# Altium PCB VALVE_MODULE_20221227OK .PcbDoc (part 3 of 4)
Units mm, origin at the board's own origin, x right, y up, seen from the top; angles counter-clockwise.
Board outline 260.15 x 142.01 mm, 2 copper layers (Top Layer, Bottom Layer); 455 components, 212 nets, 1302 pads, 385 vias.
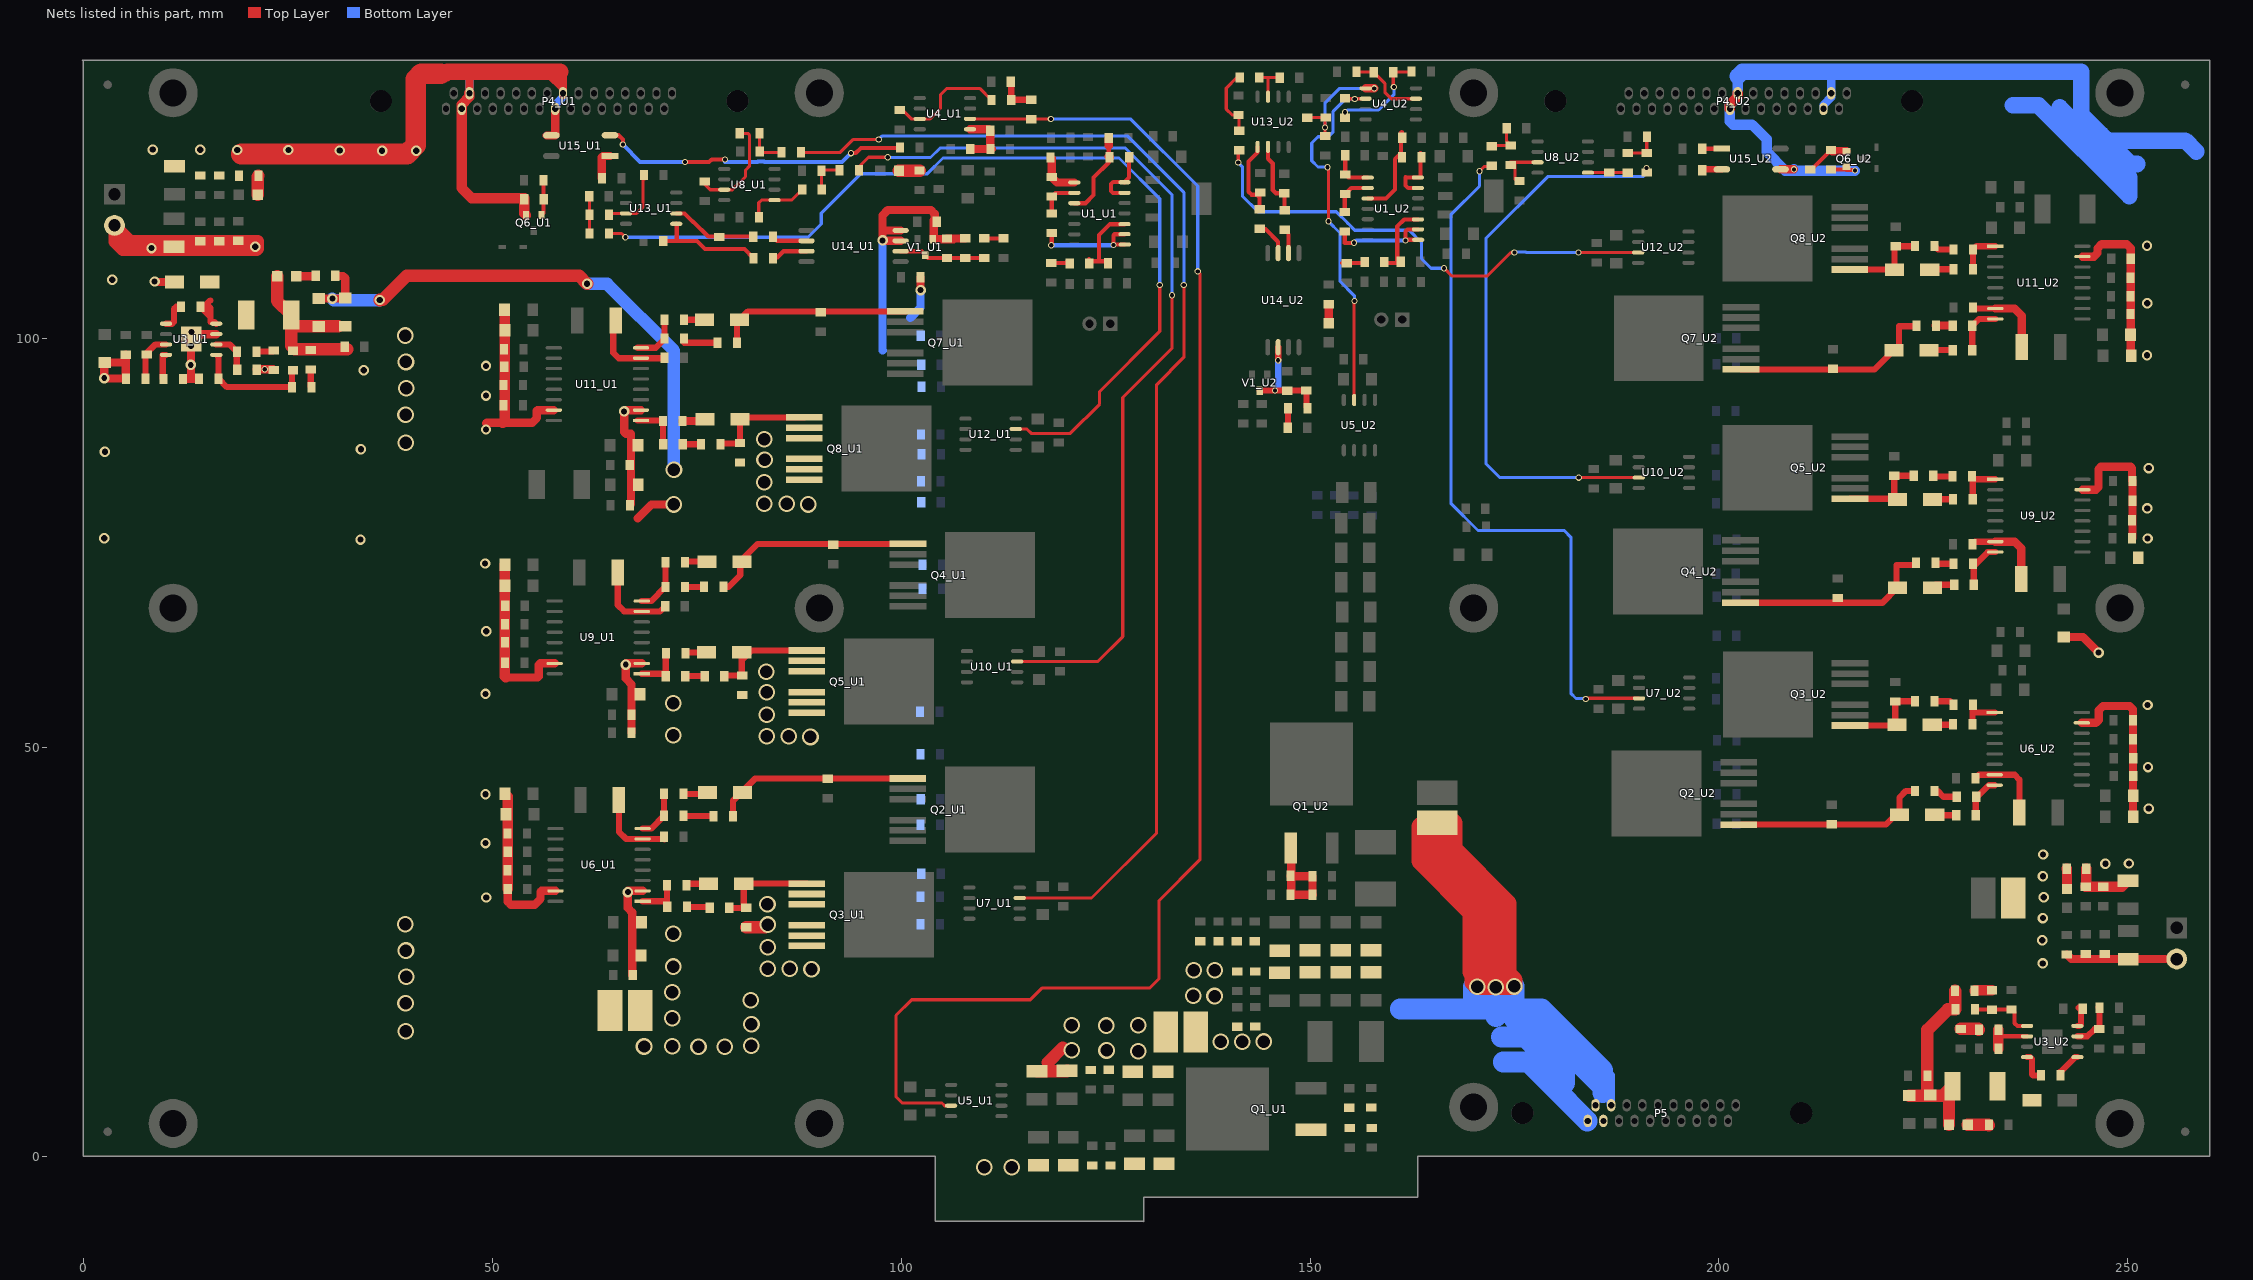
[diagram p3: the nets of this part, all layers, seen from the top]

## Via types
v1: diameter 0.762, hole 0.508, Top Layer to Bottom Layer, 142 vias
v2: diameter 2.032, hole 1.524, Top Layer to Bottom Layer, 140 vias
v3: diameter 1.27, hole 0.762, Top Layer to Bottom Layer, 77 vias
v4: diameter 1.27, hole 0.711, Top Layer to Bottom Layer, 14 vias
v5: diameter 1.778, hole 1.27, Top Layer to Bottom Layer, 12 vias

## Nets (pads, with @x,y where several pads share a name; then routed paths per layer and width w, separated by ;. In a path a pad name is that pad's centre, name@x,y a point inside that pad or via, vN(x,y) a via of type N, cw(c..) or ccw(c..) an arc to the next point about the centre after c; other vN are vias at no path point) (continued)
ISO_GND_U1: C5_U1.2 C6_U1.2 C7_U1.1 C8_U1.1 C9_U1.1 C10_U1.1 C11_U1.1 C41_U1.2 C42_U1.2 C43_U1.2 C44_U1.2 C49_U1.2 C50_U1.2 C51_U1.2 C52_U1.2 C66_U1.2 C67_U1.2 C68_U1.2 C103_U1.2 P2_U1.2 P4_U1.2 P4_U1.8 P4_U1.17 P4_U1.23 Q6_U1.2 R8_U1.1 R21_U1.1 R31_U1.2 R33_U1.2 R48_U1.2 R50_U1.2 R58_U1.1 R63_U1.2 R65_U1.2 U6_U1.15 U9_U1.15 U11_U1.15 U15_U1.4 | length 214.5
  Top Layer w1.016: P4_U1.17@47.231,129.952 47.231,131.788 47.625,132.182 57.048,132.182 ; 49.276,89.611 49.352,89.687 51.308,89.687 54.915,89.687 54.915,89.713 55.474,90.272 55.474,91.135 55.55,91.211 U11_U1.15@57.549,91.211 ; 51.689,58.547 51.714,58.522 55.575,58.522 55.702,58.649 55.702,60.046 55.905,60.249 U9_U1.15@57.651,60.249 ; R33_U1.2@51.918,32.664 51.918,31.115 52.273,30.759 55.22,30.759 55.931,31.471 55.931,32.334 56.032,32.436 U6_U1.15@57.752,32.436 ; R58_U1.1@53.924,117.018 R58_U1.1@53.924,117.119 ; U15_U1.4@56.693,124.79 57.683,124.79 57.709,124.816 P4_U1.8@57.709,128.047 ; P4_U1.23@58.661,129.952 P4_U1.23@58.661,130.569 ; 57.048,132.182 P4_U1.23@58.661,130.569 ; 57.048,132.182 58.344,132.182 58.661,131.864 P4_U1.23@58.661,130.569
  Top Layer w1.27: P4_U1.17@47.231,129.952 47.231,129.527 46.279,128.575 P4_U1.2@46.279,128.047 46.279,118.364 47.523,117.119 R58_U1.1@53.924,117.119 ; 51.308,89.687 51.537,89.916 C66_U1.2@51.537,103.48 ; C49_U1.2@51.562,72.288 C50_U1.2@51.562,69.723 C52_U1.2@51.562,65.049 R48_U1.2@51.562,62.814 R50_U1.2@51.562,60.35 51.562,58.674 51.689,58.547 ; C41_U1.2@51.587,44.298 51.918,43.967 C43_U1.2@51.918,37.211 R33_U1.2@51.918,32.664 ; R58_U1.1@53.924,117.018 53.924,115.291 Q6_U1.2@54.153,115.062
  Top Layer w1.524: 3.835,111.811 P2_U1.2@3.835,113.792 5.74,111.887 21.336,111.887 21.336,110.922 21.234,110.82 4.826,110.82 3.835,111.811
  Top Layer w2.032: 43.688,132.349 44.272,132.349 44.526,132.603 58.344,132.603
  Top Layer w2.54: 19.329,122.53 39.599,122.53 40.665,123.596 40.665,131.674 41.341,132.349 43.688,132.349
  Bottom Layer w1.016: P4_U1.17@47.231,129.952 47.231,131.788 47.701,132.258 58.369,132.258 58.661,131.966 P4_U1.23@58.661,129.952 58.661,129.476 57.709,128.524 P4_U1.8@57.709,128.047
  other v2: 39.446,15.265 39.421,18.694 39.497,21.92 39.472,25.146 39.37,28.372 39.446,87.224 39.421,90.653 39.497,93.878 39.472,97.104 39.37,100.33
  other v3: 49.276,31.623 49.2,38.278 49.2,44.247 49.2,56.515 49.276,64.186 49.149,72.466 49.251,88.849 49.251,92.989 49.251,96.622 8.357,111.023 21.031,111.201 36.551,122.911 40.716,122.911 31.369,122.961 18.847,123.012 25.095,123.012 14.326,123.038 8.509,123.063
ISO_GND_U2: C5_U2.2 C6_U2.2 C7_U2.1 C8_U2.1 C9_U2.1 C10_U2.1 C11_U2.1 C41_U2.2 C42_U2.2 C43_U2.2 C44_U2.2 C49_U2.2 C50_U2.2 C51_U2.2 C52_U2.2 C66_U2.2 C67_U2.2 C68_U2.2 C103_U2.2 P2_U2.2 P4_U2.2 P4_U2.8 P4_U2.17 P4_U2.23 Q6_U2.2 R8_U2.1 R21_U2.1 R31_U2.2 R33_U2.2 R48_U2.2 R50_U2.2 R58_U2.1 R63_U2.2 R65_U2.2 U6_U2.15 U9_U2.15 U11_U2.15 U15_U2.4 | length 228.2
  Top Layer w0.508: R58_U2.1@213.69,120.625 Q6_U2.2@215.24,120.625 ; Q6_U2.2@215.595,120.98 Q6_U2.2@215.24,120.625 ; v1(216.611,120.498) 216.611,120.548 216.586,120.574 215.57,120.574 215.519,120.625 Q6_U2.2@215.24,120.625
  Top Layer w1.016: U15_U2.4@207.518,120.65 v1(209.169,120.65) ; C50_U2.2@242.164,63.475 244.5,63.475 v3(246.405,61.57) ; C8_U2.1@242.519,24.663 243.078,24.105 C5_U2.2@250.038,24.105 P2_U2.2@255.956,24.105 ; U6_U2.15@244.355,52.984 246.075,52.984 246.431,53.34 246.431,54.534 246.939,55.042 250.215,55.042 250.622,54.635 R33_U2.2@250.622,53.315 R31_U2.2@250.622,50.952 250.622,41.504 C42_U2.2@250.647,41.478 ; U9_U2.15@244.432,81.483 246.101,81.483 246.405,81.788 246.405,83.998 246.685,84.277 250.342,84.277 250.495,84.125 250.495,82.601 R50_U2.2@250.546,82.55 R48_U2.2@250.546,80.112 250.546,75.59 C51_U2.2@250.495,75.54 ; U11_U2.15@244.432,109.982 245.847,109.982 246.278,110.414 246.278,110.998 246.786,111.506 249.834,111.506 250.342,110.998 R65_U2.2@250.342,109.703 250.342,97.892 C66_U2.2@250.393,97.841
  Top Layer w1.27: P4_U2.23@201.336,128.047 201.336,128.565 202.288,129.517 P4_U2.8@202.288,129.952 ; R8_U2.1@244.907,35.154 244.907,33.02 C7_U2.1@244.831,32.944 C11_U2.1@246.964,32.944 249.25,32.944 C6_U2.2@249.987,33.68
  Bottom Layer w1.016: P4_U2.17@212.766,128.047 212.766,128.514 213.718,129.466 P4_U2.2@213.718,129.952 213.718,132.56 213.69,132.588
  Bottom Layer w1.27: 202.311,132.029 202.288,132.006 P4_U2.8@202.288,129.952 202.288,129.441 201.336,128.489 P4_U2.23@201.336,128.047 201.336,126.502 201.727,126.111 204.038,126.111 205.816,124.333 205.816,122.784 208.102,120.498 v1@209.321,120.498 ; v1(209.169,120.65) v1@209.321,120.498 ; v1(216.611,120.498) v1@209.321,120.498
  Bottom Layer w2.032: 202.311,132.029 202.87,132.588 213.69,132.588 244.272,132.588 244.272,127.381 ; 235.941,128.499 235.941,128.473 239.065,128.473 250.165,117.373 250.165,119.685 244.272,125.578 244.272,125.628 ; 241.656,128.245 244.272,125.628 ; 251.155,121.31 250.342,121.31 247.498,124.155 ; 258.343,122.834 257.023,124.155 247.498,124.155 ; 244.272,125.628 244.272,127.381 ; 244.272,125.628 244.958,124.943 246.71,124.943 ; 244.272,127.381 246.71,124.943 ; 246.71,124.943 247.498,124.155
  other v3: 239.573,23.571 239.522,26.416 239.598,29.108 239.7,31.648 239.598,34.239 247.244,35.763 250.114,35.789 239.624,36.881 252.552,42.494 252.451,47.574 252.4,55.169 252.4,75.514 252.349,79.197 252.527,84.125 252.324,97.917 252.349,104.292 252.324,111.303
NetC13_U1_1: C13_U1.1 D2_U1.2 L1_U1.2 U3_U1.8 | length 6.6
  Top Layer w0.762: 15.57,104.623 C13_U1.1@14.808,103.861 ; U3_U1.8@16.281,101.778 16.078,101.981 15.57,101.981 15.57,102.641 ; C13_U1.1@14.808,103.861 C13_U1.1@14.351,103.861 15.57,102.641 ; C13_U1.1@14.808,103.861 15.418,103.861 15.57,103.708 15.57,102.641
NetC13_U1_2: C13_U1.2 U3_U1.1 | length 3.6
  Top Layer w0.762: U3_U1.1@10.135,101.778 10.871,101.778 11.1,102.006 11.1,103.581 11.379,103.861 C13_U1.2@11.963,103.861
NetC13_U2_1: C13_U2.1 D2_U2.2 L1_U2.2 U3_U2.8 | length 3.7
  Top Layer w0.762: U3_U2.8@237.668,12.116 238.023,12.116 238.277,11.862 238.277,9.982 238.379,9.881 C13_U2.1@239.37,9.881
NetC13_U2_2: C13_U2.2 U3_U2.1 | length 3.3
  Top Layer w0.762: C13_U2.2@241.757,9.881 241.757,10.338 243.535,12.116 U3_U2.1@243.815,12.116
NetC14_U1_1: C14_U1.1 R13_U1.1 R14_U1.2 U4_U1.5 | length 7.5
  Top Layer w1.016: U4_U1.5@108.433,125.552 110.719,125.552 C14_U1.1@110.896,125.374 110.896,123.317 111.074,123.139 R13_U1.1@108.458,123.139
NetC14_U2_1: C14_U2.1 R13_U2.1 R14_U2.2 U4_U2.5 | length 15.2
  Top Layer w0.381: C14_U2.1@149.682,126.975 R14_U2.2@151.917,126.975 ; R13_U2.1@151.841,124.714 R14_U2.2@151.841,126.822
  Top Layer w1.016: U4_U2.5@156.794,130.556 v1(157.861,130.556)
  Bottom Layer w0.381: v1(151.816,125.781) 151.816,128.753 153.619,130.556 v1(157.861,130.556)
NetC21_U1_1: C21_U1.1 C22_U1.1 C23_U1.1 D3_U1.1 L1_U1.1 R20_U1.2 R40_U1.1 | length 22.1
  Top Layer w1.524: D3_U1.1@23.724,107.569 23.724,104.572 L1_U1.1@25.451,102.845 25.451,101.092 ; 31.217,101.448 25.806,101.448 25.451,101.092 ; R40_U1.1@32.309,98.679 30.124,98.679 25.857,98.679 25.451,99.085 25.451,101.092
NetC21_U2_1: C21_U2.1 C22_U2.1 C23_U2.1 D3_U2.1 L1_U2.1 R20_U2.2 R40_U2.1 | length 24.9
  Top Layer w1.524: C22_U2.1@223.241,7.417 227.406,7.417 L1_U2.1@228.117,8.128 ; C21_U2.1@225.806,7.468 225.476,7.798 R40_U2.1@225.476,9.855 225.476,15.443 227.99,17.958 C23_U2.1@228.905,17.958 228.905,20.193 R20_U2.2@228.854,20.244 ; D3_U2.1@228.117,3.861 L1_U2.1@228.117,8.128 ; L1_U2.1@228.549,8.56 L1_U2.1@228.117,8.128
NetC23_U1_2: C23_U1.2 R19_U1.1 R22_U1.2 U3_U1.5 | length 14.2
  Top Layer w0.762: 16.535,97.714 16.561,97.688 R22_U1.2@16.561,95.047 17.577,94.031 R19_U1.1@25.552,94.031 25.552,95.987 C23_U1.2@25.654,96.088
NetC23_U2_2: C23_U2.2 R19_U2.1 R22_U2.2 U3_U2.5 | length 8
  Top Layer w0.508: C23_U2.2@231.292,17.958 231.318,17.932 R22_U2.2@235.763,17.932 236.144,17.551 236.144,16.256 236.499,15.9 236.525,15.926 U3_U2.5@237.668,15.926
NetC26_U1_2: C26_U1.2 U3_U1.4 | length 3.4
  Top Layer w0.762: C26_U1.2@9.83,95.021 9.728,95.123 9.728,97.942 10.109,97.942 U3_U1.4@10.135,97.968
NetC26_U2_2: C26_U2.2 U3_U2.4 | length 2.7
  Top Layer w0.762: U3_U2.4@243.815,15.926 244.069,15.926 244.246,16.104 244.246,17.907 C26_U2.2@243.992,18.161
NetC27_U1_2: C27_U1.2 C28_U1.2 U3_U1.6 | length 5.1
  Top Layer w0.762: U3_U1.6@16.281,99.238 17.932,99.238 C28_U1.2@18.796,98.374 18.796,96.266 C27_U1.2@18.847,96.215
NetC27_U2_2: C27_U2.2 C28_U2.2 U3_U2.6 | length 5.8
  Top Layer w0.508: 234.163,14.656 U3_U2.6@237.668,14.656
  Top Layer w1.27: C27_U2.2@234.163,13.157 234.163,14.656 C28_U2.2@234.163,15.469
NetC28_U1_1: C28_U1.1 R25_U1.2 | length 2.2
  Top Layer w0.762: C28_U1.1@21.184,98.374 23.19,98.374 R25_U1.2@23.317,98.501
NetC28_U2_1: C28_U2.1 R25_U2.2 | length 2.3
  Top Layer w1.524: R25_U2.2@229.54,15.57 231.673,15.57 C28_U2.1@231.775,15.469
NetC31_U1_1: C31_U1.1 R28_U1.2 R29_U1.1 | length 4.7
  Top Layer w0.762: C31_U1.1@113.411,131.343 113.462,131.293 R28_U1.2@113.462,129.134 113.487,129.159 R29_U1.1@115.926,129.159
NetC31_U2_1: C31_U2.1 R28_U2.2 R29_U2.1 | length 12.5
  Top Layer w0.381: R29_U2.1@154.28,127.152 v1(154.28,127.635) v1@154.28,127.711 ; v1(160.249,130.708) 160.172,130.785 R28_U2.2@160.172,132.537 160.198,132.563 162.357,132.563 C31_U2.1@162.408,132.613
  Bottom Layer w0.381: v1(154.28,127.635) 154.559,127.914 158.394,127.914 160.249,129.769 v1(160.249,130.708)
NetC32_U1_1: C32_U1.1 D6_U1.2 U6_U1.7 | length 9.8
  Top Layer w0.762: D6_U1.2@65.507,43.561 65.507,39.649 66.37,38.786 U6_U1.7@68.402,38.786 71.044,38.786 C32_U1.1@71.069,38.76
NetC32_U2_1: C32_U2.1 D6_U2.2 U6_U2.7 | length 9.8
  Top Layer w0.762: C32_U2.1@231.369,46.228 231.775,46.634 U6_U2.7@233.705,46.634 236.144,46.634 236.728,46.05 D6_U2.2@236.728,42.012
NetC33_U1_1: C33_U1.1 R28_U1.1 U4_U1.3 | length 14.9
  Top Layer w0.381: C33_U1.1@99.822,127.914 99.885,127.978 100.089,127.978 101.244,126.822 U4_U1.3@102.286,126.822 103.556,126.822 104.826,128.092 104.826,129.769 105.613,130.556 109.601,130.556 111.023,129.134 R28_U1.1@111.074,129.134
NetC33_U2_1: C33_U2.1 R28_U2.1 U4_U2.3 | length 9.3
  Top Layer w0.381: C33_U2.1@155.677,132.563 157.759,132.563 R28_U2.1@157.785,132.537 159.156,131.166 159.156,130.073 159.944,129.286 U4_U2.3@162.941,129.286
NetC45_U1_1: C45_U1.1 R43_U1.2 R44_U1.1 | length 4.9
  Top Layer w0.381: R43_U1.2@82.677,125.044 82.677,122.885 C45_U1.1@82.728,122.834 82.829,122.733 R44_U1.1@85.369,122.733
NetC45_U2_1: C45_U2.1 R43_U2.2 R44_U2.1 | length 4.5
  Top Layer w0.381: R44_U2.1@172.339,123.571 R43_U2.2@174.549,123.571 174.041,124.079 C45_U2.1@174.041,125.679
NetC46_U1_1: C46_U1.1 R43_U1.1 U8_U1.3 | length 13
  Top Layer w0.381: C46_U1.1@75.641,119.177 76.657,118.161 U8_U1.3@78.384,118.161 79.375,118.161 80.975,119.761 80.975,120.548 81.458,121.031 81.458,124.866 81.28,125.044 R43_U1.1@80.289,125.044
NetC46_U2_1: C46_U2.1 R43_U2.1 U8_U2.3 | length 5.5
  Top Layer w0.381: R43_U2.1@174.447,121.514 R43_U2.1@175.133,121.514 ; C46_U2.1@175.057,119.431 175.057,121.437 R43_U2.1@175.133,121.514 ; U8_U2.3@177.825,121.514 R43_U2.1@175.133,121.514
NetC47_U1_2: C47_U1.2 D11_U1.2 U9_U1.7 | length 10.4
  Top Layer w0.762: D11_U1.2@65.354,71.374 65.354,67.386 66.142,66.599 U9_U1.7@68.301,66.599 70.536,66.599 C47_U1.2@71.171,67.234
NetC47_U2_2: C47_U2.2 D11_U2.2 U9_U2.7 | length 10.2
  Top Layer w0.762: C47_U2.2@230.988,74.828 231.292,75.133 U9_U2.7@233.782,75.133
  Top Layer w1.016: U9_U2.7@233.782,75.133 236.144,75.133 236.957,74.32 D11_U2.2@236.957,70.561
NetC48_U1_1: C48_U1.1 R56_U1.2 R57_U1.1 | length 4.5
  Top Layer w0.381: R56_U1.2@90.297,118.186 90.272,118.212 C48_U1.1@90.272,120.472 90.348,120.548 R57_U1.1@92.456,120.548
NetC48_U2_1: C48_U2.1 R56_U2.2 R57_U2.1 | length 4.3
  Top Layer w0.381: R56_U2.2@188.849,122.631 191.135,122.631 R57_U2.1@191.16,122.657 191.16,124.587 C48_U2.1@191.211,124.638
NetC53_U1_1: C53_U1.1 R56_U1.1 U8_U1.5 | length 7.8
  Top Layer w0.381: C53_U1.1@82.652,114.783 82.601,114.833 82.601,116.561 82.931,116.891 U8_U1.5@84.531,116.891 86.614,116.891 R56_U1.1@87.909,118.186
NetC53_U2_1: C53_U2.1 R56_U2.1 U8_U2.5 | length 4.9
  Top Layer w0.381: U8_U2.5@183.972,120.244 R56_U2.1@188.849,120.244
NetC54_U1_2: C54_U1.2 D16_U1.2 U11_U1.7 | length 10.7
  Top Layer w0.762: D16_U1.2@64.821,102.667 64.821,98.222 65.481,97.561 67.767,97.561 C54_U1.2@70.841,97.561
NetC54_U2_2: C54_U2.2 D16_U2.2 U11_U2.7 | length 10.2
  Top Layer w0.762: C54_U2.2@231.064,103.759 231.191,103.632 U11_U2.7@233.782,103.632
  Top Layer w1.016: U11_U2.7@233.782,103.632 236.144,103.632 237.007,102.768 D16_U2.2@237.007,98.958
NetC61_U1_1: C61_U1.1 R69_U1.2 R70_U1.1 | length 4.6
  Top Layer w0.381: C61_U1.1@61.874,117.348 61.9,117.323 R69_U1.2@61.9,115.087 R70_U1.1@61.9,112.801
NetC61_U2_1: C61_U2.1 R69_U2.2 R70_U2.1 | length 8.5
  Top Layer w0.381: R70_U2.1@141.326,125.374 141.326,127.229 C61_U2.1@141.249,127.305 140.462,127.305 139.751,128.016 139.751,130.581 141.046,131.877 R69_U2.2@141.402,131.877
NetC64_U1_1: C64_U1.1 R69_U1.1 U13_U1.3 | length 8.2
  Top Layer w0.381: R69_U1.1@64.287,115.087 64.465,115.265 U13_U1.3@66.37,115.265 67.666,115.265 68.428,116.027 68.428,119.456 C64_U1.1@68.707,119.456
NetC64_U2_1: C64_U2.1 R69_U2.1 U13_U2.3 | length 4.8
  Top Layer w0.381: R69_U2.1@143.789,131.877 146.279,131.877 C64_U2.1@146.304,131.851 ; U13_U2.3@144.856,129.54 144.856,131.775
NetC69_U1_2: C69_U1.2 R75_U1.2 R76_U1.1 U14_U1.2 V1_U1.3 | length 10.6
  Top Layer w0.508: U14_U1.2@99.949,110.642 102.489,110.642 V1_U1.3@102.946,110.185 103.302,109.83 R76_U1.1@107.848,109.83 R75_U1.2@110.185,109.83
NetC69_U2_2: C69_U2.2 R75_U2.2 R76_U2.1 U14_U2.2 V1_U2.3 | length 13.4
  Top Layer w0.762: V1_U2.3@143.84,93.599 R76_U2.1@149.555,93.599 149.555,91.592 R75_U2.2@149.708,91.44 ; v1(146.101,97.307) U14_U2.2@146.101,98.908
  Bottom Layer w0.762: v1(145.72,93.624) 146.101,94.005 v1(146.101,97.307)
NetD1_U1_2: D1_U1.2 R8_U1.2 | length 2.4
  Top Layer w1.524: D1_U1.2@21.336,117.551 21.336,119.761 R8_U1.2@21.438,119.863
NetD1_U2_2: D1_U2.2 R8_U2.2 | length 2.5
  Top Layer w1.27: R8_U2.2@242.519,35.154 242.545,35.128 D1_U2.2@242.545,32.664
NetD3_U1_2: D3_U1.2 R16_U1.1 | length 2.4
  Top Layer w1.016: D3_U1.2@26.035,107.569 28.397,107.569 R16_U1.1@28.448,107.62
NetD3_U2_2: D3_U2.2 R16_U2.1 | length 2.6
  Top Layer w1.524: D3_U2.2@230.429,3.861 232.943,3.861 R16_U2.1@232.994,3.81
NetD5_U1_1: D5_U1.1 Q2_U1.1 R27_U1.2 R30_U1.1 | length 24.4
  Top Layer w0.762: R27_U1.2@79.451,41.58 79.451,43.459 82.169,46.177 Q2_U1.1@100.813,46.177
NetD5_U1_2: D5_U1.2 R23_U1.2 | length 3.1
  Top Layer w0.762: R23_U1.2@73.33,44.298 76.142,44.298 D5_U1.2@76.32,44.475
NetD5_U2_1: D5_U2.1 Q2_U2.1 R27_U2.2 R30_U2.1 | length 23.9
  Top Layer w0.762: Q2_U2.1@202.413,40.538 220.396,40.538 D5_U2.1@221.539,41.681 ; D5_U2.1@222.072,41.758 222.072,43.866 222.86,44.653 R27_U2.2@223.952,44.653
NetD5_U2_2: D5_U2.2 R23_U2.2 | length 3.2
  Top Layer w0.762: D5_U2.2@225.839,41.681 R23_U2.2@229.006,41.681
NetD9_U1_1: D9_U1.1 Q3_U1.1 R36_U1.2 R37_U1.2 | length 12.4
  Top Layer w0.762: R36_U1.2@78.994,30.353 80.747,30.353 80.772,30.378 D9_U1.1@80.772,33.299 80.797,33.325 Q3_U1.1@88.468,33.325
NetD9_U1_2: D9_U1.2 R32_U1.2 | length 2.8
  Top Layer w0.762: R32_U1.2@73.787,33.122 73.965,33.299 D9_U1.2@76.472,33.299
NetD9_U2_1: D9_U2.1 Q3_U2.1 R36_U2.2 R37_U2.2 | length 10.8
  Top Layer w0.762: Q3_U2.1@216.027,52.654 221.437,52.654 221.539,52.756 R37_U2.2@221.539,55.575 221.59,55.626 R36_U2.2@223.977,55.626
NetD9_U2_2: D9_U2.2 R32_U2.2 | length 2.8
  Top Layer w0.762: D9_U2.2@225.839,52.756 228.549,52.756 R32_U2.2@228.6,52.807
NetD10_U1_1: D10_U1.1 Q4_U1.1 R42_U1.2 R47_U1.2 | length 25.7
  Top Layer w0.762: R42_U1.2@78.308,69.621 78.918,69.621 80.34,71.044 80.34,72.72 82.474,74.854 Q4_U1.1@100.838,74.854
NetD10_U1_2: D10_U1.2 R39_U1.2 | length 2.7
  Top Layer w0.762: R39_U1.2@73.584,72.593 73.685,72.695 D10_U1.2@76.269,72.695
NetD10_U2_1: D10_U2.1 Q4_U2.1 R42_U2.2 R47_U2.2 | length 25.2
  Top Layer w0.762: Q4_U2.1@202.616,67.666 219.989,67.666 D10_U2.1@221.818,69.494 221.717,69.596 221.717,72.263 223.799,72.263 R42_U2.2@224.079,72.542
NetD10_U2_2: D10_U2.2 R39_U2.2 | length 2.8
  Top Layer w0.762: D10_U2.2@226.118,69.494 226.499,69.875 R39_U2.2@228.752,69.875
NetD14_U1_1: D14_U1.1 Q5_U1.1 R53_U1.2 R54_U1.2 | length 13.4
  Top Layer w0.762: R53_U1.2@78.257,58.776 R54_U1.2@80.569,58.776 ; R54_U1.2@80.518,58.725 D14_U1.1@80.518,61.595 ; 80.645,60.782 81.686,61.824 Q5_U1.1@88.468,61.824
NetD14_U1_2: D14_U1.2 R49_U1.2 | length 2.5
  Top Layer w0.762: R49_U1.2@73.736,61.57 D14_U1.2@76.193,61.57
NetD14_U2_1: D14_U2.1 Q5_U2.1 R53_U2.2 R54_U2.2 | length 10.5
  Top Layer w0.762: Q5_U2.1@216.002,80.366 221.259,80.366 221.285,80.391 221.437,80.543 R54_U2.2@221.437,83.185 R53_U2.2@223.799,83.185
NetD14_U2_2: D14_U2.2 R49_U2.2 | length 3.1
  Top Layer w0.762: D14_U2.2@225.585,80.391 225.661,80.315 R49_U2.2@228.625,80.315
NetD15_U1_1: D15_U1.1 Q7_U1.1 R61_U1.2 R62_U1.2 | length 23.6
  Top Layer w0.762: R61_U1.2@79.934,99.441 79.934,101.93 D15_U1.1@80.264,102.26 81.28,103.276 Q7_U1.1@100.508,103.276
NetD15_U1_2: D15_U1.2 R59_U1.2 | length 2.5
  Top Layer w0.762: R59_U1.2@73.457,102.26 D15_U1.2@75.964,102.26
NetD15_U2_1: D15_U2.1 Q7_U2.1 R61_U2.2 R62_U2.2 | length 25
  Top Layer w0.762: Q7_U2.1@202.692,96.19 219.024,96.19 D15_U2.1@221.386,98.552 221.996,99.162 221.996,101.473 224.053,101.473 R61_U2.2@224.13,101.549
NetD15_U2_2: D15_U2.2 R59_U2.2 | length 2.9
  Top Layer w0.762: D15_U2.2@225.686,98.552 228.549,98.552 R59_U2.2@228.575,98.527
NetD18_U1_1: D18_U1.1 Q8_U1.1 R67_U1.2 R68_U1.2 | length 13.3
  Top Layer w0.762: R67_U1.2@77.927,87.046 78.003,87.122 80.315,87.122 D18_U1.1@80.315,90.094 D18_U1.1@80.543,90.322 ; D18_U1.1@80.62,90.322 Q8_U1.1@88.163,90.322
NetD18_U1_2: D18_U1.2 R64_U1.2 | length 2.8
  Top Layer w1.016: R64_U1.2@73.279,89.891 75.812,89.891 D18_U1.2@76.015,90.094
NetD18_U2_1: D18_U2.1 Q8_U2.1 R67_U2.2 R68_U2.2 | length 10.9
  Top Layer w0.508: D18_U2.1@221.437,108.407 D18_U2.1@221.463,108.382 ; R68_U2.2@221.437,111.074 221.463,111.1 R68_U2.2@221.615,111.252 R68_U2.2@221.64,111.277
  Top Layer w0.762: Q8_U2.1@215.976,108.407 D18_U2.1@221.437,108.407 ; D18_U2.1@221.463,108.382 R68_U2.2@221.463,111.1 ; R68_U2.2@221.615,111.252 223.952,111.252 R67_U2.2@223.977,111.277
NetD18_U2_2: D18_U2.2 R64_U2.2 | length 3
  Top Layer w0.508: R64_U2.2@228.6,108.382 R64_U2.2@228.651,108.433
  Top Layer w0.762: D18_U2.2@225.763,108.382 225.813,108.433 R64_U2.2@228.651,108.433
NetD19_U1_2: D19_U1.2 R71_U1.2 | length 2.5
  Top Layer w1.524: D19_U1.2@99.746,120.472 102.235,120.472 R71_U1.2@102.26,120.498
NetD19_U2_2: D19_U2.2 R71_U2.2 | length 2.3
  Top Layer w1.016: D19_U2.2@152.298,101.829 R71_U2.2@152.298,104.165
NetQ1_U1_1: Q1_U1.1 R15_U1.2 R18_U1.1 R34_U1.2 R38_U1.1
NetQ1_U2_1: Q1_U2.1 R15_U2.2 R18_U2.1 R34_U2.2 R38_U2.1 | length 13.3
  Top Layer w1.016: R18_U2.1@147.625,34.265 147.676,34.214 R18_U2.1@147.701,34.214 ; Q1_U2.1@147.625,37.694 147.701,37.617 R18_U2.1@147.701,34.214 ; R15_U2.2@150.317,31.953 R15_U2.2@150.292,31.979 ; R18_U2.1@147.701,34.214 R34_U2.2@150.292,34.214 R15_U2.2@150.292,31.979 ; R18_U2.1@147.701,34.214 147.701,31.953 150.266,31.953 R15_U2.2@150.292,31.979
NetQ6_U1_1: Q6_U1.1 R55_U1.1 R58_U1.2 | length 4.3
  Top Layer w0.508: Q6_U1.1@56.032,115.062 56.286,115.316 R55_U1.1@56.286,119.304
NetQ6_U2_1: Q6_U2.1 R55_U2.1 R58_U2.2 | length 5.5
  Top Layer w0.508: R55_U2.1@211.15,120.65 211.328,120.65 R58_U2.2@213.69,123.012
  Top Layer w1.016: R58_U2.2@213.69,123.012 213.843,122.86 Q6_U2.1@215.595,122.86
NetR1_U1_1: R1_U1.1 R5_U1.1 U1_U1.1 | length 5.5
  Top Layer w1.016: R5_U1.1@118.288,122.098 118.415,121.971 R1_U1.1@118.415,119.71 119.075,119.05 U1_U1.1@121.183,119.05
NetR1_U1_2: R1_U1.2 R2_U1.1 U1_U1.2 | length 5
  Top Layer w0.508: R2_U1.1@118.415,115.265 R1_U1.2@118.415,117.323 118.872,117.78 U1_U1.2@121.183,117.78
NetR1_U2_1: R1_U2.1 R5_U2.1 U1_U2.1 | length 5.2
  Top Layer w0.508: R5_U2.1@154.305,122.352 R1_U2.1@154.305,120.015 154.686,119.634 U1_U2.1@157.048,119.634
NetR1_U2_2: R1_U2.2 R2_U2.1 U1_U2.2 | length 5.3
  Top Layer w0.508: R2_U2.1@154.254,115.443 154.254,117.577 R1_U2.2@154.305,117.627 155.042,118.364 U1_U2.2@157.048,118.364
NetR2_U1_2: R2_U1.2 U1_U1.8 U1_U1.9 | length 13.2
  Top Layer w0.508: v1(118.364,111.379) 118.389,111.379 118.415,111.354 R2_U1.2@118.415,112.878 ; U1_U1.9@127.33,112.725 126.086,112.725 125.959,112.598 v1(125.959,111.404) 126.009,111.455 U1_U1.8@127.356,111.455
  Bottom Layer w0.508: v1(118.364,111.379) 125.959,111.379 v1(125.959,111.404)
NetR2_U2_2: R2_U2.2 U1_U2.8 U1_U2.9 | length 13.2
  Top Layer w0.508: 154.254,111.887 154.254,111.658 ; R2_U2.2@154.254,113.055 154.254,111.658 ; v1@155.016,111.658 154.254,111.658 ; U1_U2.9@163.195,113.309 161.9,113.309 161.671,113.081 v1(161.671,111.963) 161.747,112.039 U1_U2.8@163.22,112.039
  Bottom Layer w0.508: v1@155.346,111.658 155.651,111.963 v1(161.671,111.963)
  other v1: 155.372,111.684
NetR3_U1_2: R3_U1.2 R7_U1.1 U1_U1.10 | length 9.3
  Top Layer w0.508: R7_U1.1@122.961,109.652 123.19,109.423 124.206,109.423 ; R3_U1.2@125.298,109.423 124.206,109.423 ; U1_U1.10@127.33,113.944 125.527,113.944 124.206,112.624 124.206,109.423
NetR3_U2_2: R3_U2.2 R7_U2.1 U1_U2.10 | length 9.2
  Top Layer w0.508: R7_U2.1@159.41,109.195 R3_U2.2@160.934,109.195 ; R3_U2.2@161.087,109.347 R3_U2.2@160.934,109.195 ; U1_U2.10@163.195,114.529 161.519,114.529 160.655,113.665 160.655,109.474 R3_U2.2@160.934,109.195
NetR6_U1_1: R6_U1.1 R12_U1.1 U1_U1.3 | length 10.7
  Top Layer w0.508: U1_U1.3@121.183,116.51 122.53,116.51 123.546,117.526 123.546,119.659 125.4,121.514 125.4,122.225 125.4,123.495
  Top Layer w1.016: R6_U1.1@125.4,122.225 R6_U1.1@125.501,122.123 ; 125.4,123.495 R12_U1.1@125.4,124.485
NetR6_U1_2: R6_U1.2 U1_U1.13 U1_U1.14 | length 7.6
  Top Layer w0.508: U1_U1.13@127.33,117.78 125.908,117.78 125.679,118.008 125.679,118.847 125.933,119.101 127.305,119.101 U1_U1.14@127.33,119.075 127.889,119.634 R6_U1.2@127.889,122.123
NetR6_U2_1: R6_U2.1 R12_U2.1 U1_U2.3 | length 11.2
  Top Layer w0.508: U1_U2.3@157.048,117.094 159.309,117.094 160.401,118.186 160.401,121.895 161.138,122.631 161.138,125.146 161.214,125.222
NetR6_U2_2: R6_U2.2 U1_U2.13 U1_U2.14 | length 7.5
  Top Layer w0.508: U1_U2.13@163.195,118.364 162.001,118.364 161.671,118.694 161.671,119.685 161.696,119.659 U1_U2.14@163.195,119.659 163.5,119.659 163.525,119.634 R6_U2.2@163.525,122.631
NetR7_U1_2: R7_U1.2 R10_U1.2 | length 2.1
  Top Layer w0.508: R10_U1.2@118.364,109.195 120.117,109.195 R7_U1.2@120.383,109.461
NetR7_U2_2: R7_U2.2 R10_U2.2 | length 2.3
  Top Layer w0.508: R10_U2.2@153.924,109.22 156.159,109.22 156.185,109.195
NetR17_U1_2: R17_U1.2 R24_U1.1 U3_U1.3 | length 6
  Top Layer w0.762: R24_U1.1@7.62,95.072 7.62,98.019 8.839,99.238 U3_U1.3@10.135,99.238
NetR17_U2_2: R17_U2.2 R24_U2.1 U3_U2.3 | length 5.8
  Top Layer w0.762: U3_U2.3@243.815,14.656 245.034,14.656 245.923,15.545 R17_U2.2@246.507,15.545 R24_U2.1@246.507,18.136 R24_U2.1@246.431,18.212
NetR19_U1_2: R19_U1.2 R20_U1.1 | length 2.2
  Top Layer w0.762: R20_U1.1@27.838,96.19 27.838,94.132 R19_U1.2@27.94,94.031
NetR19_U2_2: R19_U2.2 R20_U2.1 | length 2.2
  Top Layer w1.27: R20_U2.1@231.242,20.244 231.292,20.295 R19_U2.2@233.375,20.295
NetR23_U1_1: R23_U1.1 R26_U1.1 U6_U1.8 | length 6
  Top Layer w0.762: U6_U1.8@68.402,40.056 69.469,40.056 R26_U1.1@71.018,41.605 R23_U1.1@71.018,44.298
NetR23_U2_1: R23_U2.1 R26_U2.1 U6_U2.8 | length 5.1
  Top Layer w0.762: R23_U2.1@231.394,41.681 231.394,43.764 232.994,45.364 U6_U2.8@233.705,45.364
NetR26_U1_2: R26_U1.2 R27_U1.1 | length 3.7
  Top Layer w0.762: R26_U1.2@73.406,41.605 73.431,41.58 R27_U1.1@77.064,41.58
NetR26_U2_2: R26_U2.2 R27_U2.1 | length 3
  Top Layer w0.762: R27_U2.1@226.339,44.653 226.72,44.653 227.432,43.942 R26_U2.2@229.057,43.942
NetR29_U1_2: R29_U1.2 U4_U1.6 U5_U1.7 | length 181.5
  Top Layer w0.381: U5_U1.7@106.121,6.172 105.334,6.172 105.004,6.502 100.152,6.502 99.39,7.264 99.39,17.221 101.295,19.126 115.799,19.126 117.221,20.549 130.378,20.549 131.547,21.717 131.547,31.267 136.525,36.246 136.525,107.925 v1(136.271,108.179) ; U4_U1.6@108.433,126.822 v1(118.313,126.822)
  Bottom Layer w0.381: v1(118.313,126.822) 118.77,126.822 118.745,126.797 128.092,126.797 136.271,118.618 v1(136.271,108.179)
NetR29_U2_2: R29_U2.2 U4_U2.6 U5_U2.7 | length 45.8
  Top Layer w0.381: v1(152.248,114.3) v1@152.248,120.809 ; R29_U2.2@154.33,129.286 v1@155.727,129.286 ; U5_U2.7@155.397,92.456 155.397,104.521 v1(155.423,104.546) ; 155.956,129.286 v1@155.727,129.286 ; U4_U2.6@156.794,129.286 v1@155.727,129.286
  Bottom Layer w0.381: v1(152.248,114.3) 153.67,112.878 153.67,106.959 155.423,105.207 v1(155.423,104.546) ; v1@152.248,120.929 150.978,120.929 150.216,121.691 150.216,123.876 150.978,124.638 152.222,124.638 152.832,125.247 152.832,127.737 154.356,129.261 v1(155.473,129.261)
  other v1: 152.146,120.904
NetR32_U1_1: R32_U1.1 R35_U1.1 U6_U1.1 | length 5.7
  Top Layer w0.762: U6_U1.1@68.402,31.166 71.374,31.166 71.399,31.191 ; R32_U1.1@71.399,33.122 71.399,31.191 ; R35_U1.1@71.425,30.48 71.399,30.505 71.399,31.191
NetR32_U2_1: R32_U2.1 R35_U2.1 U6_U2.1 | length 5.2
  Top Layer w0.762: R32_U2.1@230.988,52.807 230.988,54.127 ; R35_U2.1@231.064,55.194 230.988,55.118 230.988,54.127 ; U6_U2.1@233.705,54.254 231.115,54.254 230.988,54.127
NetR35_U1_2: R35_U1.2 R36_U1.1 | length 2.8
  Top Layer w0.762: R35_U1.2@73.812,30.48 76.479,30.48 R36_U1.1@76.606,30.353
NetR35_U2_2: R35_U2.2 R36_U2.1 | length 2.5
  Top Layer w0.762: R36_U2.1@226.365,55.626 228.244,55.626 R35_U2.2@228.676,55.194
NetR39_U1_1: R39_U1.1 R41_U1.1 U9_U1.8 | length 6.6
  Top Layer w0.762: U9_U1.8@68.301,67.869 69.469,67.869 R41_U1.1@71.196,69.596 R39_U1.1@71.196,72.593
NetR39_U2_1: R39_U2.1 R41_U2.1 U9_U2.8 | length 5.6
  Top Layer w0.762: R39_U2.1@231.14,69.875 231.14,72.136 232.867,73.863 U9_U2.8@233.782,73.863
NetR41_U1_2: R41_U1.2 R42_U1.1 | length 2.3
  Top Layer w0.762: R41_U1.2@73.584,69.596 75.895,69.596 R42_U1.1@75.921,69.621
NetR41_U2_2: R41_U2.2 R42_U2.1 | length 2.3
  Top Layer w0.762: R42_U2.1@226.466,72.542 226.568,72.441 R41_U2.2@228.676,72.441
NetR44_U1_2: R44_U1.2 U7_U1.7 | length 150.2
  Top Layer w0.381: R44_U1.2@87.757,122.733 92.583,122.733 94.17,124.32 94.183,124.308 v1(97.282,124.308) ; U7_U1.7@114.503,31.572 123.292,31.572 131.242,39.522 131.242,94.336 134.569,97.663 v1(134.569,106.528)
  Bottom Layer w0.381: v1(97.282,124.308) 97.714,124.739 127.66,124.739 134.569,117.831 v1(134.569,106.528)
NetR44_U2_2: R44_U2.2 U7_U2.7 | length 88.4
  Top Layer w0.381: v1(170.713,120.421) 171.298,121.006 R44_U2.2@172.517,121.006 ; v1(183.718,55.905) 183.794,55.982 U7_U2.7@190.221,55.982
  Bottom Layer w0.381: v1@170.713,120.498 170.713,118.593 167.221,115.1 167.221,79.819 170.536,76.505 181.077,76.505 181.889,75.692 181.889,56.591 182.524,55.956 v1@183.794,55.956
NetR45_U1_2: R45_U1.2 U15_U1.1 | length 3.7
  Top Layer w1.016: R45_U1.2@63.424,119.558 63.398,119.583 63.398,122.123 63.551,122.276 U15_U1.1@64.414,122.276
NetR45_U2_2: R45_U2.2 U15_U2.1 | length 2.4
  Top Layer w0.508: R45_U2.2@197.942,123.165 200.33,123.165 U15_U2.1@200.355,123.19
NetR46_U1_2: R46_U1.2 U15_U1.3 | length 38.1
  Top Layer w0.508: U15_U1.3@64.414,124.816 65.456,124.816 65.989,124.282 v1(65.989,123.673) ; v1(73.584,121.564) 76.505,121.564 76.53,121.539 76.86,121.869 v1(78.486,121.869) ; v1(93.878,122.631) 94.463,122.631 95.098,123.266 99.822,123.266 R46_U1.2@99.873,123.317
  Bottom Layer w0.508: v1(65.989,123.673) 68.097,121.564 v1(73.584,121.564) ; v1@78.486,121.539 82.436,121.539 82.487,121.59 83.223,121.59 83.274,121.539 92.786,121.539 v1(93.878,122.631)
NetR46_U2_2: R46_U2.2 U15_U2.3 | length 2.5
  Top Layer w0.762: R46_U2.2@197.942,120.548 198.044,120.65 U15_U2.3@200.355,120.65
NetR49_U1_1: R49_U1.1 R52_U1.1 U9_U1.1 | length 5.7
  Top Layer w0.762: U9_U1.1@68.301,58.979 70.968,58.979 R52_U1.1@70.993,58.953 ; R52_U1.1@71.222,58.674 R49_U1.1@71.222,61.697
NetR49_U2_1: R49_U2.1 R52_U2.1 U9_U2.1 | length 5.7
  Top Layer w0.762: R52_U2.1@230.937,83.109 R52_U2.1@231.013,83.033 ; R49_U2.1@231.013,80.315 R52_U2.1@231.013,83.033 ; U9_U2.1@233.782,82.753 231.292,82.753 R52_U2.1@231.013,83.033
NetR52_U1_2: R52_U1.2 R53_U1.1 | length 2.2
  Top Layer w0.762: R52_U1.2@73.787,58.699 R53_U1.1@75.997,58.699
NetR52_U2_2: R52_U2.2 R53_U2.1 | length 2.4
  Top Layer w0.762: R53_U2.1@226.187,83.185 226.263,83.109 R52_U2.2@228.549,83.109
NetR57_U1_2: R57_U1.2 U10_U1.7 | length 115.8
  Top Layer w0.381: v1(98.374,122.123) 96.012,122.123 R57_U1.2@95.047,121.158 ; U10_U1.7@114.198,60.477 124.054,60.477 127.102,63.525 127.102,92.761 133.121,98.781 v1(133.121,105.258) ; R57_U1.2@95.047,121.158 94.844,120.955 R57_U1.2@94.844,120.548 95.047,120.752 R57_U1.2@95.047,121.158
  Bottom Layer w0.381: v1(98.374,122.123) 98.4,122.098 103.607,122.098 104.775,123.266 ; 107.213,123.266 104.775,123.266 ; v1(133.121,105.258) 133.121,117.551 127.406,123.266 104.775,123.266
NetR57_U2_2: R57_U2.2 U10_U2.7 | length 70.5
  Top Layer w0.381: v1(182.855,82.956) U10_U2.7@190.195,82.956
  Bottom Layer w0.381: v1(182.855,82.956) 173.228,82.956 171.501,84.684 171.501,112.192 179.07,119.761 190.703,119.761 191.135,120.193 v1(191.135,120.828)
NetR59_U1_1: R59_U1.1 R60_U1.1 U11_U1.8 | length 6.1
  Top Layer w0.762: U11_U1.8@67.767,98.831 70.002,98.831 71.069,99.898 R59_U1.1@71.069,102.26
NetR59_U2_1: R59_U2.1 R60_U2.1 U11_U2.8 | length 6.2
  Top Layer w0.762: R59_U2.1@230.962,98.527 R60_U2.1@230.962,101.524 231.8,102.362 U11_U2.8@233.782,102.362
NetR60_U1_2: R60_U1.2 R61_U1.1 | length 4.1
  Top Layer w0.762: R60_U1.2@73.482,99.441 R61_U1.1@77.546,99.441
NetR60_U2_2: R60_U2.2 R61_U2.1 | length 2.1
  Top Layer w1.016: R61_U2.1@226.517,101.549 228.549,101.549 R60_U2.2@228.575,101.524
NetR64_U1_1: R64_U1.1 R66_U1.1 U11_U1.1 | length 6.1
  Top Layer w0.762: U11_U1.1@67.767,89.941 R64_U1.1@70.917,89.941 ; R64_U1.1@70.841,89.941 R64_U1.1@70.891,89.891 70.891,87.071 R66_U1.1@70.917,87.046
NetR64_U2_1: R64_U2.1 R66_U2.1 U11_U2.1 | length 5.3
  Top Layer w0.762: R64_U2.1@231.038,108.433 231.038,110.82 R66_U2.1@231.064,110.846 231.47,111.252 U11_U2.1@233.782,111.252
NetR66_U1_2: R66_U1.2 R67_U1.1 | length 2.2
  Top Layer w0.762: R66_U1.2@73.304,87.046 R67_U1.1@75.54,87.046
NetR66_U2_2: R66_U2.2 R67_U2.1 | length 2.5
  Top Layer w0.762: R67_U2.1@226.365,111.277 226.797,110.846 R66_U2.2@228.676,110.846
NetR70_U1_2: R70_U1.2 U12_U1.7 | length 114.6
  Top Layer w0.381: R70_U1.2@64.287,112.801 65.837,112.801 v1(66.294,112.344) ; U12_U1.7@114.021,88.9 115.367,88.9 115.9,88.367 120.701,88.367 124.282,91.948 124.282,93.497 131.623,100.838 v1(131.623,106.502)
  Bottom Layer w0.381: v1@66.243,112.344 v1(66.294,112.344) 88.621,112.344 90.246,113.97 90.246,115.291 95.072,120.117 103.2,120.117 105.131,122.047 126.644,122.047 131.623,117.069 v1(131.623,106.502)
NetR70_U2_2: R70_U2.2 U12_U2.7 | length 60.7
  Top Layer w0.381: v1(141.224,121.488) R70_U2.2@141.224,122.936 ; v1(166.395,108.56) 167.335,107.62 171.679,107.62 174.549,110.49 v1(174.981,110.49) ; v1(182.829,110.49) U12_U2.7@190.119,110.49
  Bottom Layer w0.381: v1(141.224,121.488) 141.732,120.98 141.732,117.399 143.662,115.468 153.213,115.468 154.635,114.046 ; 154.559,114.046 154.635,114.046 ; v1(166.395,108.56) 164.795,108.56 163.627,109.728 163.627,111.709 162.128,113.208 155.473,113.208 154.635,114.046 ; v1(174.981,110.49) 175.031,110.541 176.378,110.541 176.428,110.49 v1(182.829,110.49)
NetR72_U1_1: R72_U1.1 R73_U1.2 U13_U1.5 | length 14.1
  Top Layer w0.508: R72_U1.1@70.917,111.887 72.568,111.887 ; U13_U1.5@72.517,113.995 72.568,113.944 72.568,111.887 ; R73_U1.2@81.966,109.779 80.848,110.896 76.022,110.896 75.032,111.887 72.568,111.887
NetR72_U2_1: R72_U2.1 R73_U2.2 U13_U2.5 | length 9.7
  Top Layer w0.508: U13_U2.5@143.586,123.393 143.586,122.707 142.469,121.59 142.469,117.907 142.824,117.551 143.485,117.551 143.84,117.196 ; R73_U2.2@143.84,115.773 143.84,117.196 ; R72_U2.1@143.916,117.831 143.84,117.754 143.84,117.196
NetR73_U1_1: R73_U1.1 U14_U1.7 | length 3.9
  Top Layer w0.508: 84.887,109.906 85.623,110.642 U14_U1.7@88.443,110.642
NetR73_U2_1: R73_U2.1 U14_U2.7 | length 4.3
  Top Layer w0.508: R73_U2.1@143.84,113.386 143.866,113.36 144.54,113.36 146.101,111.8 U14_U2.7@146.101,110.414
NetR74_U1_1: R74_U1.1 R75_U1.1 | length 2.3
  Top Layer w0.508: R75_U1.1@110.185,112.217 R74_U1.1@112.522,112.217
NetR74_U2_1: R74_U2.1 R75_U2.1 | length 2.4
  Top Layer w0.762: R74_U2.1@147.269,89.052 147.32,89.103 R75_U2.1@147.32,91.44
NetR77_U1_1: R77_U1.1 R78_U1.2 U13_U1.6 | length 10.7
  Top Layer w0.508: U13_U1.6@72.517,115.265 73.533,115.265 74.574,114.224 74.574,114.275 76.429,112.42 R78_U1.2@81.94,112.42
NetR77_U2_1: R77_U2.1 R78_U2.2 U13_U2.6 | length 9.2
  Top Layer w0.508: U13_U2.6@144.856,123.393 144.856,121.945 145.44,121.361 145.44,118.11 145.821,117.729 R77_U2.1@146.863,117.729 146.888,117.704 R78_U2.2@146.888,115.646
NetR78_U1_1: R78_U1.1 U14_U1.6 | length 4.3
  Top Layer w0.508: R78_U1.1@84.328,112.42 84.836,111.912 U14_U1.6@88.443,111.912
NetR78_U2_1: R78_U2.1 U14_U2.6 | length 2.3
  Top Layer w0.508: U14_U2.6@147.371,110.414 147.371,112.725
PGND: C34.2 C35.2 C36.2 C37.2 C38.2 C39.2 C40.2 C94.2 C95.2 C96.2 C97.2 C98.2 C99.2 C100.2 C101.2 C102.2 P5.9 P5.10 P5.19 P5.20 R79.1 R80.1 | length 180.9
  Top Layer w2.032: 169.901,22.581 169.901,21.234 v2(170.434,20.701) 170.485,20.752 v2(174.981,20.752) 174.981,21.565 173.965,22.581
  Top Layer w2.54: R80.1@163.652,40.234 163.652,36.119 169.901,29.87 169.901,22.581 171.958,22.581 ; R80.1@165.659,40.615 165.659,36.982 171.958,30.683 171.958,22.581 ; 167.284,37.541 173.965,30.861 173.965,22.581 171.958,22.581 ; 167.361,34.493 R80.1@167.361,40.716
  Bottom Layer w1.016: 185.115,11.532 186.76,9.887 P5.9@186.76,6.223
  Bottom Layer w2.54: 161.036,18.009 169.291,18.009 ; v2@170.205,20.676 v2(172.72,20.676) 172.72,17.069 ; v2@172.974,20.752 v2(174.981,20.752) 174.981,16.764 ; 173.406,14.58 176.327,14.58 ; 173.634,11.532 176.689,11.532 179.454,8.766 ; 173.965,18.593 173.38,18.009 ; 181.127,8.966 181.14,8.979 181.14,13.119 ; P5.20@183.902,4.318 179.454,8.766 ; 185.801,7.772 185.801,8.458 ; 169.291,18.009 169.951,18.669 169.951,20.701 171.577,19.075 171.577,18.009 ; 169.291,18.009 171.577,18.009 ; 171.577,18.009 173.38,18.009 ; 173.38,18.009 176.251,18.009 ; 176.251,18.009 178.308,18.009 185.801,10.516 185.801,8.458 ; 176.251,18.009 177.127,17.132 ; 176.327,14.58 179.454,11.452 ; 176.327,14.58 176.327,16.332 177.127,17.132 ; 177.127,17.132 179.454,14.805 ; 179.454,8.766 179.454,11.452 ; 179.454,11.452 179.454,14.805 ; 179.454,14.805 181.14,13.119 ; 181.14,13.119 185.801,8.458
  other v2: 139.065,13.97 141.732,13.995 144.348,14.021 138.328,19.583 135.712,19.609 135.763,22.733 138.354,22.733
PGND_U1: C15_U1.2 C16_U1.2 C17_U1.2 C18_U1.2 C19_U1.2 C20_U1.2 C21_U1.2 C22_U1.2 C24_U1.2 C25_U1.1 C26_U1.1 C27_U1.1 C29_U1.1 C30_U1.1 C69_U1.1 C70_U1.2 C71_U1.2 C72_U1.2 C73_U1.2 C74_U1.2 C75_U1.2 C76_U1.2 C77_U1.2 C78_U1.2 C79_U1.2 C80_U1.2 C81_U1.2 C82_U1.2 C83_U1.2 C84_U1.2 C85_U1.2 C86_U1.2 C87_U1.2 C88_U1.2 C89_U1.2 C90_U1.2 C91_U1.2 C92_U1.2 C93_U1.2 C106_U1.2 C107_U1.2 C108_U1.2 C109_U1.2 C110_U1.2 C111_U1.2 C112_U1.2 C113_U1.2 D2_U1.1 Q3_U1.2 Q3_U1.3 Q3_U1.5 Q3_U1.6 Q3_U1.7 Q5_U1.2 Q5_U1.3 Q5_U1.5 Q5_U1.6 Q5_U1.7 Q8_U1.2 Q8_U1.3 Q8_U1.5 Q8_U1.6 Q8_U1.7 R16_U1.2 R21_U1.2 R22_U1.1 R24_U1.2 R25_U1.1 R37_U1.1 R54_U1.1 R68_U1.1 R76_U1.2 R79.2 U3_U1.7 U3_U1.9 U6_U1.2 U9_U1.2 U11_U1.2 U14_U1.3 U14_U1.4 V1_U1.1 | length 184.9
  Top Layer w1.016: C25_U1.1@5.207,97.993 5.207,96.901 ; v4(8.738,106.934) 8.788,106.883 D2_U1.1@11.176,106.883 ; C26_U1.1@12.217,95.021 13.183,95.021 ; R22_U1.1@14.173,95.047 14.148,95.021 13.183,95.021 ; U3_U1.7@16.281,100.508 13.818,100.508 U3_U1.9@13.208,99.898 13.183,99.873 13.183,95.021 ; C27_U1.1@21.234,96.215 v1(22.2,96.215) 23.216,96.215 R25_U1.1@23.317,96.114 ; C21_U1.2@28.829,104.851 v4(30.48,104.851) 32.004,104.851 C22_U1.2@32.055,104.902 32.055,107.34 31.775,107.62 R16_U1.2@30.886,107.62 ; v4(66.142,91.059) 66.142,88.544 66.37,88.316 66.98,88.316 66.98,79.705 C111_U1.2@66.878,79.604 ; v4@66.192,91.211 U11_U1.2@68.199,91.211 ; v4(66.345,60.096) 66.345,58.395 67.056,57.683 C107_U1.2@67.056,53.95 C109_U1.2@67.056,51.765 ; v4@66.37,60.249 U9_U1.2@68.301,60.249 ; v4(66.599,32.283) 66.599,30.353 67.132,29.82 C113_U1.2@67.132,22.149 ; v4@66.624,32.436 U6_U1.2@68.402,32.436 ; 67.818,78.003 69.494,79.68 v2(72.212,79.68) ; 97.917,113.182 U14_U1.4@99.949,113.182 ; U14_U1.3@99.949,111.912 97.79,111.912 v4(97.739,111.963) 97.739,115.037 98.374,115.672 103.657,115.672 104.115,115.214 C30_U1.1@104.115,114.579 ; v4(102.387,105.893) C29_U1.1@102.387,107.467 ; C30_U1.1@103.988,114.427 103.988,112.116 106.401,112.116 106.477,112.192 ; C69_U1.1@105.613,112.192 106.477,112.192 ; R76_U1.2@107.848,112.217 107.823,112.192 106.477,112.192 ; 5.207,96.901 5.08,97.028 C24_U1.2@2.667,97.028 2.591,96.952 v4(2.591,95.123) 2.642,95.072 R24_U1.2@5.232,95.072 5.207,95.098 5.207,96.901
  Top Layer w1.524: v3(36.271,104.673) 36.271,104.724 36.652,104.724 39.573,107.645 60.63,107.645 v3(61.62,106.655) ; R37_U1.1@81.077,27.991 83.388,27.991 v2(83.718,28.321) ; C70_U1.2@116.637,10.389 120.244,10.389 C15_U1.2@120.294,10.439 ; 117.958,11.455 119.761,13.259
  Bottom Layer w1.016: v4@97.739,111.709 97.739,98.527 97.765,98.501 ; 101.143,102.489 102.387,103.734 v4(102.387,105.893)
  Bottom Layer w1.524: v4(30.48,104.851) 30.658,104.673 v3(36.271,104.673) ; v3(61.62,106.655) 64.059,106.655 72.238,98.476 v2(72.238,83.922)
  other v2: 110.16,-1.372 113.513,-1.346 129.007,12.827 125.12,12.929 120.879,12.954 75.235,13.36 78.461,13.386 68.58,13.411 72.009,13.437 81.686,13.487 125.07,15.977 120.879,16.002 128.981,16.027 81.712,16.129 72.009,16.866 81.61,19.05 72.034,20.066 89.052,22.835 83.693,22.911 86.411,22.936 72.161,23.19 83.693,25.552 72.136,27.203 83.668,30.785 88.925,51.257 83.566,51.333 86.284,51.359 72.161,51.46 83.566,53.975 72.161,55.372 83.591,56.744 83.541,59.207 88.646,79.68 83.287,79.756 86.004,79.781 83.287,82.398 83.312,85.166 83.261,87.63
  other v3: 33.909,75.387 2.591,75.54 2.667,86.131 33.96,86.436 34.315,96.088 3.556,107.163
  other v4: 13.157,96.749 13.208,99.035 13.233,100.762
